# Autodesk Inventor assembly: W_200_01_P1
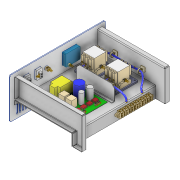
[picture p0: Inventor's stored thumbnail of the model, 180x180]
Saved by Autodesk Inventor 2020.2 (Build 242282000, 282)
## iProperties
Created: 2014-09
Part Number: W_200_01_P1
Document SubType Name: Assembly
Designer: F.Stasiak
Catalog Web Link: www.expertbooks.pl
Manager: www.cadconsulting.pl
Company: Fabian Stasiak CAD Consulting
Author: F.Stasiak
Subject: Zbiór ćwiczeń. Autodesk Inventor 2020. Kurs Professional
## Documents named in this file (18)
- C:\2020_Kurs_Professional\R2 Wiązki\W_200_01_P1.iam
- C:\2020_Kurs_Professional\R2 Wiązki\Komponenty\PCB_100_01.ipt
- C:\2020_Kurs_Professional\R2 Wiązki\Komponenty\S_150_100.ipt
- C:\2020_Kurs_Professional\R2 Wiązki\Komponenty\Switch_100_01.ipt
- C:\2020_Kurs_Professional\R2 Wiązki\Komponenty\Switch_100_02.ipt
- C:\2020_Kurs_Professional\R2 Wiązki\Komponenty\KOND_350_2300.ipt
- C:\2020_Kurs_Professional\R2 Wiązki\Komponenty\LAMP_100_01.ipt
- C:\2020_Kurs_Professional\R2 Wiązki\Komponenty\LISTWA_100_01.ipt
- C:\2020_Kurs_Professional\R2 Wiązki\Komponenty\Płyta.ipt
- C:\2020_Kurs_Professional\R2 Wiązki\Komponenty\Bok_01.ipt
- C:\2020_Kurs_Professional\R2 Wiązki\Komponenty\Bok_02.ipt
- C:\2020_Kurs_Professional\R2 Wiązki\Komponenty\Szyna_01.ipt
- C:\2020_Kurs_Professional\R2 Wiązki\Komponenty\Front_01.ipt
- C:\2020_Kurs_Professional\R2 Wiązki\Komponenty\METER_100_01.ipt
- C:\2020_Kurs_Professional\R2 Wiązki\Komponenty\Ściana_01.ipt
- C:\2020_Kurs_Professional\R2 Wiązki\Komponenty\KLIP_100_01.ipt
- C:\2020_Kurs_Professional\R2 Wiązki\W_200_01_P1\AIP\przewody i wiązki przewodów\W_200_01_P1.Wiązka przewodów1.iam
- C:\2020_Kurs_Professional\R2 Wiązki\W_200_01_P1\AIP\przewody i wiązki przewodów\W_200_01_P1.Wiązka przewodów2.iam
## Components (22 placed, 17 different names)
1. Płyta:1 — Równoległy:3, Zestawiający:1, Zestawiający:3, Zestawiający:4, Zestawiający:5, Zestawiający:6, Równoległy:4, Zestawiający:7, Zestawiający:8, Równoległy:5, Zestawiający:9, Równoległy:9, Równoległy:10, Zestawiający:13, Równoległy:14, Zestawiający:20, Równoległy:15
2. Bok_01:1 — Zestawiający:5, Zestawiający:6, Równoległy:4, Równoległy:11, Zestawiający:33, Zestawiający:34
3. Bok_02:1 — Zestawiający:7, Zestawiający:8, Równoległy:5
4. Szyna_01:1 — Zestawiający:9, Zestawiający:10, Równoległy:6, Równoległy:7, Zestawiający:11, Równoległy:14, Zestawiający:20
5. Ściana_01:1 — Równoległy:15, Zestawiający:30, Zestawiający:31
6. Front_01:1 — Równoległy:9, Równoległy:10, Zestawiający:13, Równoległy:11, Wstaw:1, Zestawiający:21, Zestawiający:22, Zestawiający:23, Zestawiający:24, Zestawiający:25, Zestawiający:26, Zestawiający:27, Zestawiający:28, Zestawiający:29
7. KLIP_100_01:1 — Zestawiający:30, Równoległy:16, Zestawiający:32, Równoległy:20, Równoległy:21
8. KLIP_100_01:2 — Zestawiający:31, Równoległy:16, Zestawiający:32, Równoległy:19, Równoległy:22
9. KLIP_100_01:3 — Zestawiający:33, Równoległy:19, Równoległy:22
10. KLIP_100_01:4 — Zestawiający:34, Równoległy:20, Równoległy:21
11. PCB_100_01:1 — Zestawiający:1
12. S_150_100:1 — Równoległy:1, Równoległy:2, Zestawiający:3
13. S_150_100:2 — Równoległy:1, Równoległy:2
14. LISTWA_100_01:1 — Zestawiający:4
15. Switch_100_01:1 — Zestawiający:23, Zestawiający:24, Zestawiający:26
16. Switch_100_02:1 — Zestawiający:21, Zestawiający:22, Zestawiający:25
17. KOND_350_2300:1 — Zestawiający:10, Równoległy:6, Równoległy:7, Równoległy:8, Zestawiający:12
18. KOND_350_2300:2 — Zestawiający:11, Równoległy:8, Zestawiający:12
19. LAMP_100_01:1 — Wstaw:1
20. METER_100_01:1 — Zestawiający:27, Zestawiający:28, Zestawiający:29
21. Wiązka przewodów1 [sub-assembly]
22. Wiązka przewodów2 [sub-assembly]
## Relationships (46: Mate 27, Flush 18, Insert 1)
- Równoległy:1 [Flush]: S_150_100:1 ↔ S_150_100:2
- Równoległy:2 [Flush]: S_150_100:1 ↔ S_150_100:2
- Równoległy:3 [Flush]: Płyta:1
- Zestawiający:1 [Mate]: Płyta:1 ↔ PCB_100_01:1
- Zestawiający:3 [Mate]: Płyta:1 ↔ S_150_100:1
- Zestawiający:4 [Mate]: Płyta:1 ↔ LISTWA_100_01:1
- Zestawiający:5 [Mate]: Płyta:1 ↔ Bok_01:1
- Zestawiający:6 [Mate]: Płyta:1 ↔ Bok_01:1
- Równoległy:4 [Flush]: Płyta:1 ↔ Bok_01:1
- Zestawiający:7 [Mate]: Płyta:1 ↔ Bok_02:1
- Zestawiający:8 [Mate]: Płyta:1 ↔ Bok_02:1
- Równoległy:5 [Flush]: Płyta:1 ↔ Bok_02:1
- Zestawiający:9 [Mate]: Płyta:1 ↔ Szyna_01:1
- Zestawiający:10 [Mate]: Szyna_01:1 ↔ KOND_350_2300:1
- Równoległy:6 [Flush]: Szyna_01:1 ↔ KOND_350_2300:1
- Równoległy:7 [Flush]: Szyna_01:1 ↔ KOND_350_2300:1
- Zestawiający:11 [Mate]: Szyna_01:1 ↔ KOND_350_2300:2
- Równoległy:8 [Flush]: KOND_350_2300:1 ↔ KOND_350_2300:2
- Zestawiający:12 [Mate]: KOND_350_2300:1 ↔ KOND_350_2300:2
- Równoległy:9 [Flush]: Płyta:1 ↔ Front_01:1
- Równoległy:10 [Flush]: Płyta:1 ↔ Front_01:1
- Zestawiający:13 [Mate]: Płyta:1 ↔ Front_01:1
- Równoległy:11 [Flush]: Bok_01:1 ↔ Front_01:1
- Równoległy:14 [Flush]: Płyta:1 ↔ Szyna_01:1
- Zestawiający:20 [Mate]: Płyta:1 ↔ Szyna_01:1
- Wstaw:1 [Insert]: Front_01:1 ↔ LAMP_100_01:1
- Zestawiający:21 [Mate]: Front_01:1 ↔ Switch_100_02:1
- Zestawiający:22 [Mate]: Front_01:1 ↔ Switch_100_02:1
- Zestawiający:23 [Mate]: Front_01:1 ↔ Switch_100_01:1
- Zestawiający:24 [Mate]: Front_01:1 ↔ Switch_100_01:1
- Zestawiający:25 [Mate]: Front_01:1 ↔ Switch_100_02:1
- Zestawiający:26 [Mate]: Front_01:1 ↔ Switch_100_01:1
- Zestawiający:27 [Mate]: Front_01:1 ↔ METER_100_01:1
- Zestawiający:28 [Mate]: Front_01:1 ↔ METER_100_01:1
- Zestawiający:29 [Mate]: Front_01:1 ↔ METER_100_01:1
- Równoległy:15 [Flush]: Płyta:1 ↔ Ściana_01:1
- Zestawiający:30 [Mate]: Ściana_01:1 ↔ KLIP_100_01:1
- Zestawiający:31 [Mate]: Ściana_01:1 ↔ KLIP_100_01:2
- Równoległy:16 [Flush]: KLIP_100_01:1 ↔ KLIP_100_01:2
- Zestawiający:32 [Mate]: KLIP_100_01:1 ↔ KLIP_100_01:2
- Zestawiający:33 [Mate]: Bok_01:1 ↔ KLIP_100_01:3
- Zestawiający:34 [Mate]: Bok_01:1 ↔ KLIP_100_01:4
- Równoległy:19 [Flush]: KLIP_100_01:2 ↔ KLIP_100_01:3
- Równoległy:20 [Flush]: KLIP_100_01:1 ↔ KLIP_100_01:4
- Równoległy:21 [Flush]: KLIP_100_01:1 ↔ KLIP_100_01:4
- Równoległy:22 [Flush]: KLIP_100_01:2 ↔ KLIP_100_01:3
